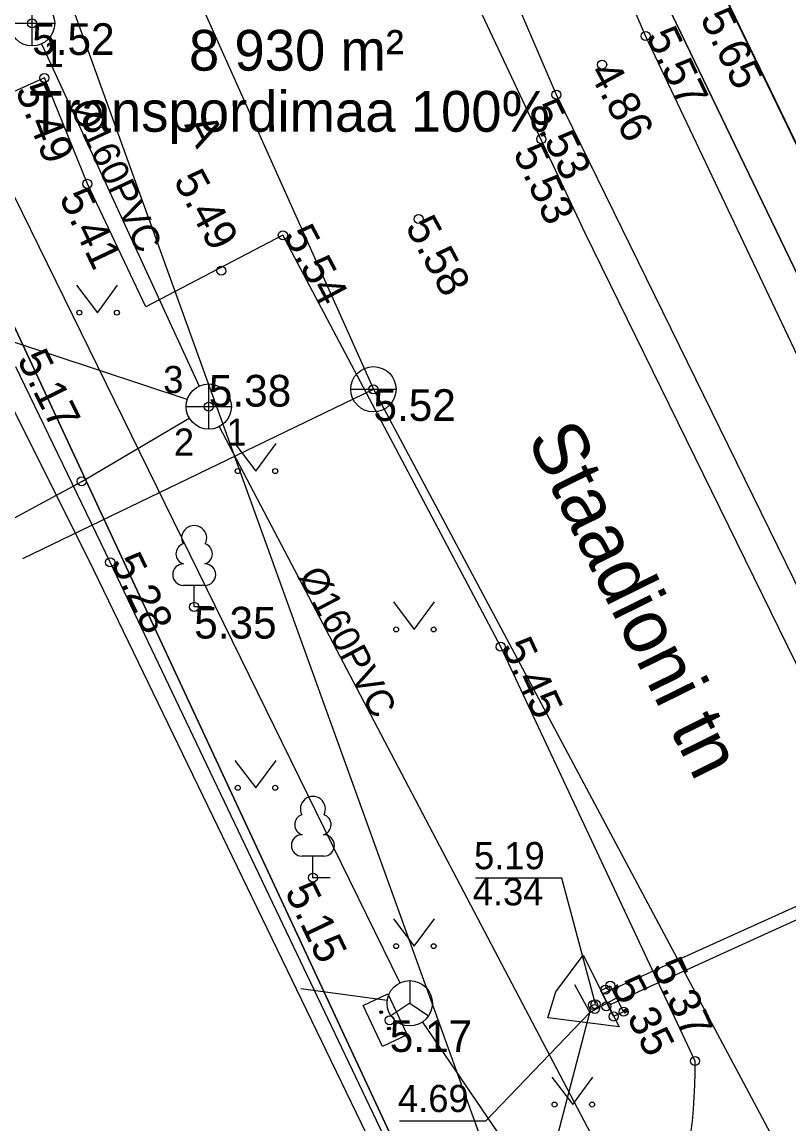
# Model space of a CAD drawing. Extents: x 473307 to 473719, y 6532843 to 6533381.
# Drawn here: x 473402.1 to 473419.05, y 6533087.54 to 6533111.89 of the extents above; entities that cross this region are included whole.
import ezdxf

# ---------------------------------------------------------------- set-up
doc = ezdxf.new("R2010")
doc.units = 0
for name, color, linetype in [('AED', 7, 'Continuous'), ('Default', 7, 'Continuous'), ('HALJASTUS', 7, 'Continuous'), ('KKAEV', 7, 'Continuous'), ('KKAEV_NR', 7, 'Continuous'), ('KORGUS', 7, 'Continuous'), ('KTRASS', 7, 'Continuous'), ('KTRASS_TEKST', 7, 'Continuous'), ('MPKAABEL', 7, 'Continuous'), ('MPOHULIIN', 7, 'Continuous'), ('PIIR', 7, 'Continuous'), ('PUU', 7, 'Continuous'), ('RAJATIS', 7, 'Continuous'), ('SIKAEV', 7, 'Continuous'), ('SIRAJATIS', 7, 'Continuous'), ('SITRASS', 7, 'Continuous'), ('SKKAEV_NR', 7, 'Continuous'), ('SKTRASS', 7, 'Continuous'), ('TEE', 7, 'Continuous'), ('TRUUP', 7, 'Continuous'), ('VEEKOGU', 7, 'Continuous'), ('VKAEV', 7, 'Continuous'), ('VTRASS', 7, 'Continuous')]:
    doc.layers.add(name, color=color, linetype=linetype)

# ---------------------------------------------------------------- blocks, each defined once
blk = doc.blocks.new('LEHTP1')
at = {"layer": 'Default'}
for p, q in [((0.48, 0.95), (-0.48, 0.95)), ((0, 0), (0, 0.95)), ((0.76, 0), (0, 0))]:
    blk.add_line(p, q, dxfattribs=at)
for centre, radius, start, end in [((0, 3.04), 0.554, 332.5799, 207.4201), ((-0.34, 2.345), 0.465, 109.0217, 253.1415), ((0.34, 2.345), 0.465, 286.8508, 70.9859), ((-0.475, 1.425), 0.475, 90.0016, 269.3953), ((0.475, 1.425), 0.475, 270.6047, 89.9984)]:
    blk.add_arc(centre, radius, start, end, dxfattribs=at)
blk = doc.blocks.new('KAKAEV')
at = {"layer": 'Default'}
for p, q in [((0, -1), (0, 1)), ((-1, 0), (1, 0))]:
    blk.add_line(p, q, dxfattribs=at)
blk.add_circle((0, 0), 1, dxfattribs=at)
blk = doc.blocks.new('VEKAEV')
at = {"layer": 'Default'}
blk.add_line((-1, 0), (1, 0), dxfattribs=at)
blk.add_circle((0, 0), 1, dxfattribs=at)
blk = doc.blocks.new('SIKAPP')
at = {"layer": 'Default'}
blk.add_lwpolyline([(-1, 0.6), (1, 0.6), (1, -0.6), (-1, -0.6)], close=True, dxfattribs=at)
for centre, radius in [((-0.4, 0), 0.0608), ((-0.4, 0), 0.0581), ((-0.4, 0), 0.0553), ((-0.4, 0), 0.0526), ((-0.4, 0), 0.0499), ((-0.4, 0), 0.0472), ((-0.4, 0), 0.0444), ((-0.4, 0), 0.0417), ((-0.4, 0), 0.039), ((-0.4, 0), 0.0363), ((-0.4, 0), 0.0335), ((-0.4, 0), 0.0308), ((-0.4, 0), 0.0281), ((-0.4, 0), 0.0254), ((-0.4, 0), 0.0226), ((-0.4, 0), 0.0199), ((-0.4, 0), 0.0172), ((-0.4, 0), 0.0145), ((-0.4, 0), 0.0117), ((-0.4, 0), 0.00902), ((-0.4, 0), 0.0063), ((-0.4, 0), 0.00358), ((-0.4, 0), 0.000852), ((0.4, 0), 0.0608), ((0.4, 0), 0.0581), ((0.4, 0), 0.0553), ((0.4, 0), 0.0526), ((0.4, 0), 0.0499), ((0.4, 0), 0.0472), ((0.4, 0), 0.0444), ((0.4, 0), 0.0417), ((0.4, 0), 0.039), ((0.4, 0), 0.0363), ((0.4, 0), 0.0335), ((0.4, 0), 0.0308), ((0.4, 0), 0.0281), ((0.4, 0), 0.0254), ((0.4, 0), 0.0226), ((0.4, 0), 0.0199), ((0.4, 0), 0.0172), ((0.4, 0), 0.0145), ((0.4, 0), 0.0117), ((0.4, 0), 0.00902), ((0.4, 0), 0.0063), ((0.4, 0), 0.00358), ((0.4, 0), 0.000852)]:
    blk.add_circle(centre, radius, dxfattribs=at)
blk = doc.blocks.new('SIKAEV')
at = {"layer": 'Default'}
for p, q in [((0, 1), (0, 0)), ((0, 0), (-0.83, -0.55)), ((0, 0), (0.83, -0.55))]:
    blk.add_line(p, q, dxfattribs=at)
blk.add_circle((0, 0), 1, dxfattribs=at)
blk = doc.blocks.new('TORVAL')
at = {"layer": 'Default'}
blk.add_lwpolyline([(-1, -1), (0, 0), (-1, 1)], dxfattribs=at)
blk = doc.blocks.new('MURU')
at = {"layer": 'Default'}
for p, q in [((-0.927, 1.213), (0, 0)), ((0, 0), (0.891, 1.213))]:
    blk.add_line(p, q, dxfattribs=at)
for centre in [(-0.802, 0), (0.856, 0)]:
    blk.add_circle(centre, 0.11, dxfattribs=at)

msp = doc.modelspace()

# ---------------------------------------------------------------- linework, layer by layer
at = {"layer": 'AED'}
for points in [[(473572.372, 6533059.989), (473562.796, 6533044.25), (473549.715, 6533022.819), (473547.153, 6533018.61), (473538.777, 6533017.059), (473515.614, 6533013.019), (473502.84, 6533010.765), (473486.499, 6533007.9), (473486.322, 6533008.043), (473484.734, 6533009.635), (473455.331, 6533045.745), (473429.609, 6533087.699), (473409.64, 6533128.98), (473398.626, 6533166.806)], [(473409.83, 6533082.929), (473411.697, 6533083.922), (473404.051, 6533099.951), (473401.968, 6533104.27)]]:
    msp.add_lwpolyline(points, dxfattribs=at)
at = {"layer": 'HALJASTUS'}
msp.add_lwpolyline([(473411.458, 6533083.707), (473403.692, 6533099.774), (473401.495, 6533104.16)], dxfattribs=at)
at = {"layer": 'KKAEV_NR'}
msp.add_lwpolyline([(473405.755, 6533103.549), (473399.915, 6533105.482), (473397.062, 6533105.482)], dxfattribs=at)
at = {"layer": 'KORGUS'}
for centre in [(473402.327, 6533111.863), (473415.881, 6533111.58), (473414.921, 6533110.948), (473402.597, 6533110.655), (473413.911, 6533110.283), (473413.577, 6533109.302), (473403.547, 6533108.314), (473410.865, 6533107.536), (473407.866, 6533107.178), (473406.508, 6533106.393), (473409.867, 6533103.775), (473406.23, 6533103.392), (473403.423, 6533101.738), (473404.051, 6533099.951), (473405.907, 6533098.966), (473412.68, 6533098.085), (473408.53, 6533092.98), (473414.993, 6533090.503), (473415.099, 6533090.594), (473414.718, 6533090.167), (473414.759, 6533090.079), (473414.774, 6533090.184), (473415.011, 6533090.137), (473415.394, 6533090.019), (473410.227, 6533089.829), (473415.174, 6533089.913), (473416.974, 6533088.927)]:
    msp.add_circle(centre, 0.1, dxfattribs=at)
at = {"layer": 'KTRASS'}
msp.add_line((473402.536, 6533111.409), (473406.019, 6533103.845), dxfattribs=at)
for points in [[(473401.764, 6533100.84), (473403.423, 6533101.738), (473405.799, 6533103.138)], [(473406.462, 6533102.949), (473417.941, 6533081.093)]]:
    msp.add_lwpolyline(points, dxfattribs=at)
at = {"layer": 'MPKAABEL'}
for points in [[(473481.096, 6533010.082), (473475.299, 6533017.476), (473469.705, 6533025.438), (473464.809, 6533033.306), (473458.878, 6533040.236), (473452.764, 6533048.342), (473452.582, 6533049.145), (473450.829, 6533050.743), (473441.685, 6533065.704), (473432.314, 6533080.211), (473428.426, 6533086.609), (473420.464, 6533103.751), (473416.16, 6533112.695), (473415.168, 6533114.011), (473413.395, 6533118.629), (473406.551, 6533134.777), (473402.712, 6533147.764), (473401.357, 6533149.404), (473399.947, 6533154.634), (473395.886, 6533169.008), (473391.18, 6533184.279)], [(473415.168, 6533114.011), (473416.16, 6533112.695), (473420.464, 6533103.751), (473428.426, 6533086.609), (473432.314, 6533080.211)]]:
    msp.add_lwpolyline(points, dxfattribs=at)
msp.add_open_spline([(473557.128, 6533166.896), (473557.202, 6533167.153), (473557.17, 6533167.374), (473557.049, 6533167.727), (473556.952, 6533168.034), (473556.879, 6533168.251), (473556.724, 6533168.7), (473555.529, 6533172.103), (473554.018, 6533176.143), (473551.965, 6533180.794), (473542.001, 6533194.467), (473528.815, 6533203.479), (473521.877, 6533205.787), (473521.549, 6533205.862), (473521.332, 6533205.91), (473521.125, 6533205.955), (473520.94, 6533205.994), (473520.783, 6533206.026), (473520.617, 6533205.983), (473520.549, 6533205.81), (473520.512, 6533205.71), (473520.33, 6533205.301), (473520.277, 6533205.676), (473520.247, 6533205.87), (473520.186, 6533205.982), (473520.155, 6533206.063), (473520.032, 6533206.188), (473519.647, 6533206.25), (473519.297, 6533206.303), (473518.91, 6533206.37), (473518.338, 6533206.457), (473517.785, 6533206.534), (473517.113, 6533206.617), (473504.722, 6533206.361), (473489.125, 6533201.073), (473481.589, 6533195.708), (473477.331, 6533191.94), (473475.034, 6533189.807), (473474.489, 6533189.292), (473474.068, 6533188.932), (473473.832, 6533188.684), (473473.679, 6533188.468), (473473.566, 6533188.217), (473473.476, 6533188.304), (473473.306, 6533188.406), (473473.134, 6533188.531), (473472.969, 6533188.652), (473471.778, 6533189.567), (473469.957, 6533190.966), (473467.155, 6533193.119), (473463.064, 6533196.262), (473458.646, 6533199.657), (473454.573, 6533202.786), (473453.666, 6533203.482), (473453.293, 6533203.769), (473452.995, 6533203.998), (473452.474, 6533204.222), (473452.213, 6533204.228), (473451.967, 6533204.234), (473451.474, 6533204.245), (473450.255, 6533204.273), (473449.394, 6533204.293), (473448.978, 6533204.302), (473448.578, 6533204.312), (473448.301, 6533204.318), (473447.638, 6533204.311), (473446.313, 6533204.297), (473445.312, 6533204.286), (473443.932, 6533204.272), (473441.622, 6533204.247), (473436.282, 6533204.191), (473430.619, 6533203.804), (473423.016, 6533203.284), (473416.174, 6533202.8), (473411.7, 6533202.424), (473406.989, 6533202.027), (473406.298, 6533201.969), (473405.901, 6533201.936), (473405.663, 6533201.916), (473405.247, 6533201.618), (473405.511, 6533201.478), (473405.706, 6533201.471), (473405.859, 6533201.485), (473406.073, 6533201.505), (473406.3, 6533201.526), (473406.699, 6533201.563), (473407.182, 6533201.607), (473407.617, 6533201.647), (473410.794, 6533201.939), (473414.597, 6533202.289), (473416.16, 6533202.433), (473416.748, 6533202.487), (473416.992, 6533202.509), (473417.116, 6533202.479), (473417.282, 6533202.408), (473417.308, 6533202.242), (473417.347, 6533201.989), (473417.396, 6533201.677), (473417.449, 6533201.337), (473417.509, 6533200.949), (473418.04, 6533197.53), (473418.813, 6533192.552), (473421.708, 6533179.543), (473422.341, 6533175.512), (473423.507, 6533169.632), (473424, 6533167.141), (473424.184, 6533166.215), (473424.244, 6533165.909), (473424.294, 6533165.662), (473424.314, 6533165.561), (473424.105, 6533164.865), (473423.816, 6533164.809), (473423.525, 6533164.753), (473422.668, 6533164.588), (473418.846, 6533164.247), (473414.425, 6533164.061), (473411.47, 6533164.651), (473411.357, 6533164.673), (473410.881, 6533164.787), (473410.433, 6533164.888), (473409.953, 6533164.731), (473409.752, 6533164.287), (473409.631, 6533163.669), (473409.502, 6533157.703), (473410.074, 6533152.735), (473410.969, 6533148.729), (473415.098, 6533136.501), (473416.702, 6533131.364), (473421.711, 6533117.606), (473423.352, 6533113.701), (473430.005, 6533097.933), (473437.623, 6533088.588), (473441.02, 6533084.73), (473450.501, 6533069.242), (473457.775, 6533058.053), (473462.215, 6533052.558), (473465.73, 6533047.735), (473467.401, 6533046.054), (473469.034, 6533044.411), (473472.353, 6533043.145), (473481.411, 6533040.582), (473489.023, 6533038.632), (473491.007, 6533038.103), (473491.686, 6533037.936), (473492.014, 6533037.852), (473492.476, 6533037.76), (473492.806, 6533038.095), (473492.829, 6533038.485), (473492.856, 6533039.18), (473492.795, 6533042.335), (473492.716, 6533044.024), (473492.683, 6533044.743), (473492.671, 6533044.987), (473492.823, 6533045.601), (473492.984, 6533045.289), (473492.985, 6533045.105), (473493.028, 6533044.585), (473493.105, 6533042.767), (473493.222, 6533039.506), (473493.206, 6533038.15), (473493.196, 6533038.01), (473493.2, 6533037.815), (473493.516, 6533037.437), (473493.94, 6533037.314), (473494.338, 6533037.204), (473496.451, 6533036.58), (473497.497, 6533036.067), (473498.11, 6533035.695), (473498.481, 6533035.454), (473498.784, 6533035.294), (473499.155, 6533035.524), (473499.568, 6533035.786), (473499.965, 6533035.642), (473500.381, 6533035.468), (473500.664, 6533035.366), (473501.255, 6533035.156), (473502.131, 6533034.826), (473503.015, 6533034.496), (473504.909, 6533033.785), (473507.281, 6533033.099), (473509.703, 6533032.392), (473510.465, 6533032.171), (473510.886, 6533032.05), (473511.297, 6533031.932), (473511.665, 6533031.668), (473511.711, 6533031.312), (473511.692, 6533030.835), (473511.632, 6533029.982), (473511.533, 6533028.937), (473511.486, 6533028.283), (473511.407, 6533027.141), (473511.358, 6533026.503), (473511.358, 6533025.257), (473511.617, 6533023.934), (473511.536, 6533023.5), (473511.414, 6533022.901), (473511.43, 6533022.205), (473511.677, 6533020.728), (473511.888, 6533019.916), (473512.37, 6533017.914), (473512.52, 6533015.831), (473512.626, 6533013.709), (473512.595, 6533013.242), (473512.387, 6533012.718), (473557.128, 6533166.896), (473512.387, 6533012.718)], degree=3, dxfattribs=at)
at = {"layer": 'MPOHULIIN'}
msp.add_lwpolyline([(473423.194, 6533272.897), (473391.791, 6533270.484), (473361.09, 6533267.919), (473364.229, 6533220.925), (473380.477, 6533175.317), (473396.165, 6533131.758), (473413.567, 6533083.532), (473430.968, 6533052.6), (473459.84, 6533016.944), (473493.252, 6532975.715), (473524.159, 6532957.128), (473561.498, 6532934.712), (473599.705, 6532914.54), (473648.184, 6532910.183)], dxfattribs=at)
at = {"layer": 'PIIR'}
for points in [[(473383.26, 6533220.83), (473372.23, 6533259.41), (473496.37, 6533266.79), (473499.84, 6533206.38), (473559.2, 6533209.37), (473561.43, 6533165.2), (473601.75, 6533167.04), (473607.56, 6533132.38), (473611.09, 6533109.85), (473618.6, 6533063.82), (473572.63, 6533056.43), (473548.5, 6533028.91), (473478.82, 6533017), (473455.33, 6533045.76), (473432.18, 6533083.36), (473429.59, 6533087.74), (473409.64, 6533129), (473385.1, 6533214.25), (473398.68, 6533216.8), (473398.11, 6533224.3)], [(473372.12, 6533096.13), (473400.27, 6533108.71), (473412.06, 6533083.41), (473383.85, 6533069.06)]]:
    msp.add_lwpolyline(points, close=True, dxfattribs=at)
for points in [[(473385.1, 6533214.25), (473409.64, 6533129), (473429.59, 6533087.74), (473432.18, 6533083.36), (473455.33, 6533045.76), (473478.82, 6533017)], [(473492.55, 6532977.62), (473473.12, 6532997.79), (473458.1, 6533015.44), (473444.45, 6533033.74), (473430.52, 6533052.35), (473416.35, 6533075.22), (473412.06, 6533083.41), (473400.27, 6533108.71), (473390.77, 6533130.51), (473383.02, 6533152.56), (473376.06, 6533174.78), (473369.76, 6533197.52)]]:
    msp.add_lwpolyline(points, dxfattribs=at)
at = {"layer": 'RAJATIS'}
msp.add_lwpolyline([(473415.099, 6533090.594), (473415.394, 6533090.019), (473415.174, 6533089.913), (473414.89, 6533090.491), (473415.099, 6533090.594)], dxfattribs=at)
at = {"layer": 'SITRASS'}
msp.add_line((473408.26, 6533090.53), (473410.174, 6533090.272), dxfattribs=at)
for points in [[(473373.611, 6533188.362), (473382.33, 6533159.31), (473384.49, 6533152.12), (473388.46, 6533141.59), (473398.2, 6533115.64), (473410.45, 6533090.654)], [(473410.951, 6533089.791), (473424.02, 6533070.59), (473439.13, 6533048.2), (473447.57, 6533035.84), (473453.172, 6533027.457)]]:
    msp.add_lwpolyline(points, dxfattribs=at)
at = {"layer": 'SKKAEV_NR'}
msp.add_lwpolyline([(473414.647, 6533090.003), (473412.347, 6533087.601), (473410.444, 6533087.601)], dxfattribs=at)
at = {"layer": 'SKTRASS'}
msp.add_line((473412.694, 6533082.493), (473414.647, 6533090.003), dxfattribs=at)
at = {"layer": 'TEE'}
for points in [[(473486.74, 6533007.668), (473486.486, 6533007.568), (473485.836, 6533006.833), (473483.72, 6533004.961), (473480.798, 6533008.092), (473475.573, 6533014.142), (473470.165, 6533020.489), (473464.659, 6533026.983), (473458.607, 6533034.554), (473452.151, 6533042.899), (473444.547, 6533053.352), (473438.634, 6533062.682), (473435.33, 6533068.051), (473426.278, 6533084.212), (473422.195, 6533091.615), (473414.542, 6533107.225), (473409.577, 6533117.788), (473405.358, 6533127.822), (473401.846, 6533136.79), (473397.087, 6533149.814), (473394.968, 6533156.469), (473393.12, 6533161.978)], [(473416.974, 6533088.927), (473412.68, 6533098.085), (473407.866, 6533107.178), (473404.842, 6533105.597), (473403.547, 6533108.314), (473402.597, 6533110.655), (473399.657, 6533109.333)]]:
    msp.add_lwpolyline(points, dxfattribs=at)
msp.add_arc((473405.794, 6533088.763), 11.181, 317.5398, 0.8409, dxfattribs=at)
at = {"layer": 'TRUUP'}
for points in [[(473414.93, 6533090.412), (473422.49, 6533093.833), (473422.6, 6533093.591), (473415.06, 6533090.154), (473414.929, 6533090.412)], [(473414.774, 6533090.184), (473414.027, 6533092.968), (473412.124, 6533092.968)]]:
    msp.add_lwpolyline(points, dxfattribs=at)
at = {"layer": 'VEEKOGU'}
for points in [[(473402.6, 6533145.241), (473405.051, 6533138.423), (473408.63, 6533128.571), (473412.37, 6533119.672), (473415.881, 6533111.58), (473424.05, 6533094.363), (473432.068, 6533080.056), (473438.112, 6533070.078), (473441.876, 6533064.003), (473447.577, 6533055.58), (473453.746, 6533046.091)], [(473452.326, 6533045.335), (473445.343, 6533054.161), (473439.616, 6533062.658), (473436.096, 6533068.575), (473429.941, 6533078.645), (473422.233, 6533093.292), (473413.911, 6533110.283), (473410.493, 6533118.237), (473406.183, 6533128.288), (473402.792, 6533137.828), (473400.309, 6533144.749)], [(473414.499, 6533091.268), (473415.294, 6533089.688), (473413.719, 6533089.885), (473413.897, 6533090.461), (473414.499, 6533091.268)], [(473414.499, 6533091.268), (473415.294, 6533089.688), (473413.719, 6533089.885), (473413.897, 6533090.461), (473414.499, 6533091.268)]]:
    msp.add_lwpolyline(points, dxfattribs=at)
at = {"layer": 'VTRASS'}
msp.add_line((473402.125, 6533100.037), (473409.867, 6533103.775), dxfattribs=at)
msp.add_lwpolyline([(473365.999, 6533272.186), (473364.518, 6533257.871), (473366.737, 6533240.392), (473372.861, 6533211.206), (473381.92, 6533180.915), (473385.845, 6533164.961), (473390.472, 6533150.34), (473401.875, 6533121.622), (473409.867, 6533103.775), (473420.281, 6533084.249), (473435.442, 6533057.262), (473447.562, 6533040.443), (473454.221, 6533030.196), (473471.046, 6533010.477), (473501.071, 6532979.442)], dxfattribs=at)

# ---------------------------------------------------------------- block references
at = {"layer": 'HALJASTUS', "xscale": 0.5, "yscale": 0.5}
for p in [(473403.771, 6533105.467), (473407.271, 6533101.967), (473410.771, 6533098.467), (473407.271, 6533094.967), (473410.771, 6533091.467), (473414.271, 6533087.967)]:
    msp.add_blockref('MURU', p, dxfattribs=at)
at = {"layer": 'KKAEV', "xscale": 0.5, "yscale": 0.5}
for p in [(473402.327, 6533111.863), (473406.23, 6533103.392)]:
    msp.add_blockref('KAKAEV', p, dxfattribs=at)
at = {"layer": 'PUU', "xscale": 0.5, "yscale": 0.5}
for p in [(473405.907, 6533098.966), (473408.53, 6533092.98)]:
    msp.add_blockref('LEHTP1', p, dxfattribs=at)
at = {"layer": 'SIKAEV', "xscale": 0.5, "yscale": 0.5}
msp.add_blockref('SIKAEV', (473410.67, 6533090.205), dxfattribs=at)
at = {"layer": 'SIRAJATIS', "xscale": 0.5000000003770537, "yscale": 0.5, "rotation": -64.88081293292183}
msp.add_blockref('SIKAPP', (473410.126, 6533089.83), dxfattribs=at)
at = {"layer": 'SKTRASS', "xscale": 0.5000000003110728, "yscale": 0.5, "rotation": -106.20634191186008}
msp.add_blockref('TORVAL', (473414.647, 6533090.003), dxfattribs=at)
at = {"layer": 'VKAEV', "xscale": 0.5, "yscale": 0.5}
msp.add_blockref('VEKAEV', (473409.867, 6533103.775), dxfattribs=at)

# ---------------------------------------------------------------- texts
at = {"layer": 'KKAEV_NR'}
for s, p in [('1', (473402.58, 6533110.9)), ('3', (473405.223, 6533103.69)), ('1', (473406.619, 6533102.527)), ('2', (473405.459, 6533102.307))]:
    msp.add_text(s, height=0.6, dxfattribs=at).set_placement(p)
at = {"layer": 'KORGUS'}
for s, rotation, p in [('5.65', 296.1219, (473417.075, 6533111.98)), ('5.57', 295.3831, (473415.881, 6533111.58)), ('4.86', 298.3495, (473414.613, 6533110.782)), ('5.49', 292.0878, (473401.948, 6533110.392)), ('5.53', 296.0951, (473413.282, 6533109.975)), ('5.53', 295.0257, (473412.943, 6533109.006)), ('5.49', 298.1501, (473405.439, 6533108.392)), ('5.41', 295.4893, (473402.915, 6533108.013)), ('5.58', 298.5538, (473410.558, 6533107.369)), ('5.54', 297.8976, (473407.866, 6533107.178)), ('5.17', 296.6084, (473401.983, 6533104.436)), ('5.28', 295.6914, (473404.051, 6533099.951)), ('5.45', 295.1209, (473412.68, 6533098.085)), ('5.15', 295.5016, (473407.898, 6533092.679)), ('5.37', 295.1209, (473415.998, 6533091.009)), ('5.35', 297.1598, (473415.099, 6533090.594))]:
    msp.add_text(s, height=0.7, rotation=rotation, dxfattribs=at).set_placement(p)
for s, p in [('5.52', (473402.327, 6533111.163)), ('5.38', (473406.23, 6533103.392)), ('5.52', (473409.867, 6533103.075)), ('5.35', (473405.907, 6533098.266)), ('5.17', (473410.227, 6533089.129))]:
    msp.add_text(s, height=0.7, dxfattribs=at).set_placement(p)
at = {"layer": 'KTRASS_TEKST'}
for rotation, p in [(294.9149, (473403.152, 6533110.017)), (297.7052, (473408.192, 6533099.656))]:
    msp.add_text('%%c160PVC', height=0.6, rotation=rotation, dxfattribs=at).set_placement(p)
at = {"layer": 'PIIR'}
for s, p in [('8 930 m²', (473405.792, 6533110.816)), ('Transpordimaa 100%', (473402.263, 6533109.466))]:
    msp.add_text(s, height=0.9, dxfattribs=at).set_placement(p)
at = {"layer": 'SKKAEV_NR'}
msp.add_text('4.69', height=0.6, dxfattribs=at).set_placement((473410.41, 6533087.801))
at = {"layer": 'TEE'}
for s, height, rotation, p in [('A', 0.7, 297.796, (473405.681, 6533109.62)), ('Staadioni tn', 1.2, 296.2406, (473413.248, 6533102.682))]:
    msp.add_text(s, height=height, rotation=rotation, dxfattribs=at).set_placement(p)
at = {"layer": 'TRUUP'}
for s, p in [('5.19', (473412.09, 6533093.168)), ('4.34', (473412.061, 6533092.368))]:
    msp.add_text(s, height=0.6, dxfattribs=at).set_placement(p)

doc.saveas('drawing.dxf')
